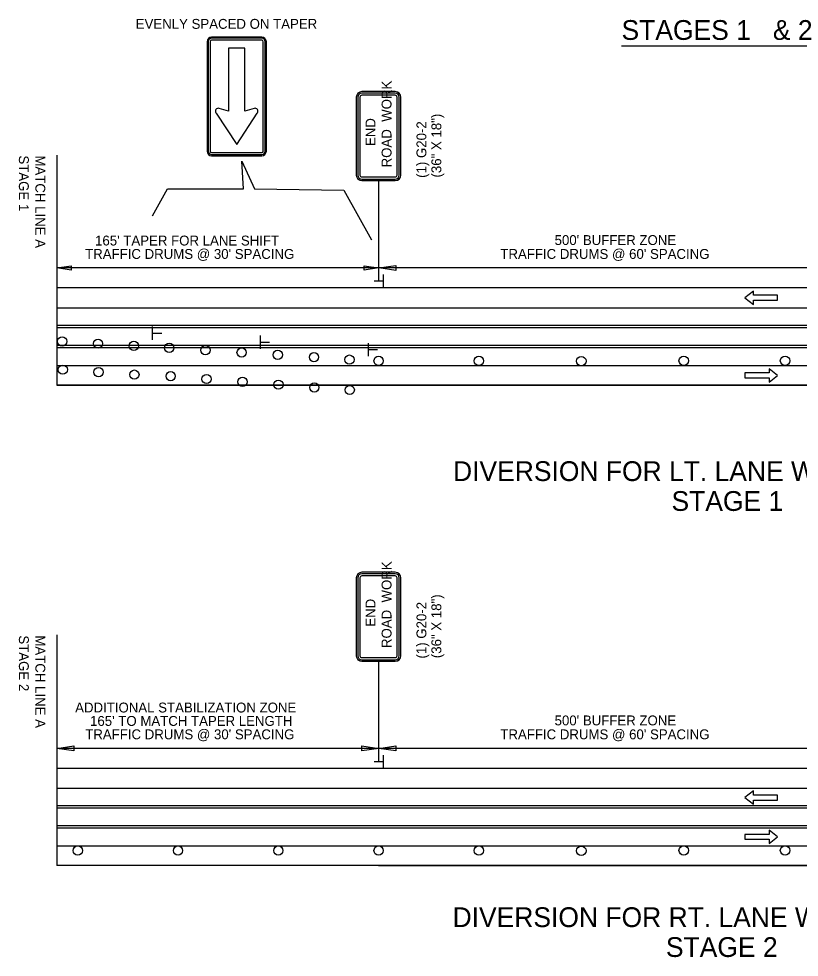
# Model space of a CAD drawing. Extents: x 1930579 to 1937984, y 596452 to 597630.
# Drawn here: x 1936470 to 1936944, y 596628 to 597198 of the extents above; entities that cross this region are included whole.
import ezdxf

# ---------------------------------------------------------------- set-up
doc = ezdxf.new("R2010")
doc.units = 0
for name, color, linetype in [('Default', 7, 'Continuous'), ('P_TC_Signs_Permanent', 7, 'Continuous'), ('P_TC_Signs_Temporary', 7, 'Continuous'), ('R_Border', 7, 'Continuous'), ('R_Striping', 7, 'Continuous')]:
    doc.layers.add(name, color=color, linetype=linetype)

msp = doc.modelspace()

# ---------------------------------------------------------------- linework, layer by layer
at = {"layer": 'Default'}
for p, q in [((1936835.84, 597181.22), (1936964.15, 597181.22)), ((1936493.11, 597114.97), (1936493.11, 596975.31)), ((1936493.11, 597046.45), (1936501.81, 597047.75)), ((1936688.44, 597046.45), (1936493.11, 597046.45)), ((1936501.81, 597045.15), (1936493.11, 597046.45)), ((1936501.81, 597047.75), (1936501.81, 597045.15)), ((1936679.75, 597045.15), (1936679.75, 597047.75)), ((1936679.75, 597047.75), (1936688.44, 597046.45)), ((1936688.44, 597046.45), (1936679.75, 597045.15)), ((1936997.05, 597046.45), (1936688.44, 597046.45)), ((1936688.53, 597046.45), (1936698.83, 597048)), ((1936698.83, 597044.9), (1936688.53, 597046.45)), ((1936698.83, 597048), (1936698.83, 597044.9)), ((1936691.23, 597042.43), (1936691.23, 597034.45)), ((1937498.74, 597034.31), (1936493.11, 597034.31)), ((1936691.12, 597038.47), (1936685.67, 597038.47)), ((1936493.11, 597022.31), (1937498.74, 597022.31)), ((1937498.74, 597011.52), (1936493.11, 597011.52)), ((1937498.74, 597010.14), (1936493.11, 597010.14)), ((1936551.31, 597002.87), (1936551.31, 597010.85)), ((1936551.43, 597006.84), (1936556.87, 597006.84)), ((1936616.72, 596997.46), (1936616.72, 597005.44)), ((1936616.84, 597001.42), (1936622.29, 597001.42)), ((1936682.29, 596992.94), (1936682.29, 597000.92)), ((1937498.74, 596999.34), (1936493.11, 596999.34)), ((1937498.74, 596998.03), (1936493.11, 596998.03)), ((1936682.4, 596996.91), (1936687.85, 596996.91)), ((1936493.11, 596987.31), (1937498.74, 596987.31)), ((1936493.11, 596975.31), (1936773.63, 596975.31)), ((1937498.74, 596975.31), (1936493.11, 596975.31)), ((1936757.75, 596975.31), (1937032.82, 596975.31)), ((1936493.11, 596823.85), (1936493.11, 596683.94)), ((1936688.44, 596765.87), (1936688.44, 596749.76)), ((1936493.11, 596755.08), (1936503.42, 596756.63)), ((1936503.42, 596756.63), (1936503.42, 596753.53)), ((1936678.23, 596753.53), (1936678.23, 596756.63)), ((1936678.23, 596756.63), (1936688.53, 596755.08)), ((1936688.53, 596755.08), (1936698.83, 596756.63)), ((1936698.83, 596756.63), (1936698.83, 596753.53)), ((1936688.53, 596755.08), (1936493.11, 596755.08)), ((1936503.42, 596753.53), (1936493.11, 596755.08)), ((1936688.53, 596755.08), (1936678.23, 596753.53)), ((1936997.05, 596755.08), (1936688.44, 596755.08)), ((1936698.83, 596753.53), (1936688.53, 596755.08)), ((1936691.23, 596750.89), (1936691.23, 596742.91)), ((1936691.12, 596746.92), (1936685.67, 596746.92)), ((1937498.74, 596742.94), (1936493.11, 596742.94)), ((1936493.11, 596730.94), (1937498.74, 596730.94)), ((1937498.74, 596720.15), (1936493.11, 596720.15)), ((1937498.74, 596718.77), (1936493.11, 596718.77)), ((1937498.74, 596707.98), (1936493.11, 596707.98)), ((1937498.74, 596706.66), (1936493.11, 596706.66)), ((1936493.11, 596695.94), (1937498.74, 596695.94)), ((1937498.74, 596683.94), (1936493.11, 596683.94)), ((1936688.44, 596683.94), (1936773.63, 596683.94)), ((1936757.75, 596683.94), (1937032.82, 596683.94))]:
    msp.add_line(p, q, dxfattribs=at)
for centre, radius in [((1936496.43, 597001.89), 2.81), ((1936518.18, 597000.54), 2.81), ((1936539.92, 596999.19), 2.81), ((1936561.41, 596998), 2.81), ((1936583.36, 596996.58), 2.81), ((1936605.32, 596995.17), 2.81), ((1936627.27, 596993.75), 2.81), ((1936649.22, 596992.34), 2.81), ((1936670.72, 596990.86), 2.81), ((1936688.44, 596990.1), 2.81), ((1936749.3, 596990.1), 2.87), ((1936811.44, 596989.95), 2.87), ((1936873.58, 596990.16), 2.87), ((1936935.06, 596990.17), 2.87), ((1936496.8, 596984.78), 2.81), ((1936518.53, 596983.27), 2.81), ((1936540.25, 596981.76), 2.81), ((1936562.28, 596980.82), 2.81), ((1936584.07, 596979.1), 2.81), ((1936605.86, 596977.39), 2.81), ((1936627.65, 596975.67), 2.81), ((1936649.45, 596973.95), 2.81), ((1936670.92, 596972.45), 2.81), ((1936505.88, 596693.1), 2.81), ((1936566.73, 596693.1), 2.81), ((1936627.59, 596693.1), 2.81), ((1936688.44, 596693.1), 2.81), ((1936749.3, 596693.1), 2.87), ((1936811.44, 596692.96), 2.87), ((1936873.58, 596693.16), 2.87), ((1936935.06, 596693.18), 2.87)]:
    msp.add_circle(centre, radius, dxfattribs=at)
at = {"layer": 'P_TC_Signs_Permanent'}
for p, q in [((1936584.33, 597183.71), (1936584.33, 597117.33)), ((1936585.08, 597183.71), (1936585.08, 597117.33)), ((1936586.2, 597183.71), (1936586.2, 597117.33)), ((1936617.51, 597186.52), (1936587.14, 597186.52)), ((1936617.51, 597185.77), (1936587.14, 597185.77)), ((1936617.51, 597184.65), (1936587.14, 597184.65)), ((1936618.45, 597117.33), (1936618.45, 597183.71)), ((1936619.58, 597117.33), (1936619.58, 597183.71)), ((1936620.33, 597117.33), (1936620.33, 597183.71)), ((1936587.14, 597116.4), (1936617.51, 597116.4)), ((1936587.14, 597115.27), (1936617.51, 597115.27)), ((1936587.14, 597114.52), (1936617.51, 597114.52))]:
    msp.add_line(p, q, dxfattribs=at)
for points in [[(1936612.96, 597143.22), (1936607.2, 597141.5), (1936607.2, 597179.77), (1936597.45, 597179.77), (1936597.45, 597141.5), (1936591.7, 597143.26)], [(1936589.88, 597140.26), (1936602.33, 597121.27), (1936614.73, 597140.27)]]:
    msp.add_lwpolyline(points, dxfattribs=at)
for centre, radius, start, end in [((1936587.14, 597183.71), 2.81, 90, 180), ((1936587.14, 597183.71), 2.06, 90, 180), ((1936587.14, 597183.71), 0.938, 90, 180), ((1936617.51, 597183.71), 2.81, 360, 90), ((1936617.51, 597183.71), 2.06, 360, 90), ((1936617.51, 597183.71), 0.937, 360, 90), ((1936591.21, 597141.53), 1.8, 74.0309, 213.4755), ((1936613.44, 597141.53), 1.76, 326.5994, 105.9691), ((1936527.15, 597099.16), 75, 33.2286, 33.4755), ((1936677.53, 597099.27), 75, 146.5994, 146.857), ((1936587.14, 597117.33), 2.81, 180, 270), ((1936587.14, 597117.33), 2.06, 180, 270), ((1936587.14, 597117.33), 0.938, 180, 270), ((1936617.51, 597117.33), 2.81, 270, 360), ((1936617.51, 597117.33), 2.06, 270, 360), ((1936617.51, 597117.33), 0.938, 270, 360)]:
    msp.add_arc(centre, radius, start, end, dxfattribs=at)
at = {"layer": 'P_TC_Signs_Temporary'}
for p, q in [((1936674.89, 597150.04), (1936674.89, 597102.79)), ((1936675.83, 597150.04), (1936675.83, 597102.79)), ((1936677.14, 597150.04), (1936677.14, 597102.79)), ((1936698.52, 597153.42), (1936678.27, 597153.42)), ((1936698.52, 597152.48), (1936678.27, 597152.48)), ((1936698.52, 597151.17), (1936678.27, 597151.17)), ((1936699.64, 597102.79), (1936699.64, 597150.04)), ((1936700.96, 597102.79), (1936700.96, 597150.04)), ((1936701.89, 597102.79), (1936701.89, 597150.04)), ((1936678.27, 597101.67), (1936698.52, 597101.67)), ((1936678.27, 597100.36), (1936698.52, 597100.36)), ((1936678.27, 597099.42), (1936698.52, 597099.42)), ((1936674.89, 596858.5), (1936674.89, 596811.25)), ((1936675.83, 596858.5), (1936675.83, 596811.25)), ((1936677.14, 596858.5), (1936677.14, 596811.25)), ((1936698.52, 596861.87), (1936678.27, 596861.87)), ((1936698.52, 596860.93), (1936678.27, 596860.93)), ((1936698.52, 596859.62), (1936678.27, 596859.62)), ((1936699.64, 596811.25), (1936699.64, 596858.5)), ((1936700.96, 596811.25), (1936700.96, 596858.5)), ((1936701.89, 596811.25), (1936701.89, 596858.5)), ((1936678.27, 596810.12), (1936698.52, 596810.12)), ((1936678.27, 596808.81), (1936698.52, 596808.81)), ((1936678.27, 596807.87), (1936698.52, 596807.87))]:
    msp.add_line(p, q, dxfattribs=at)
for centre, radius, start, end in [((1936678.27, 597150.04), 3.38, 90, 180), ((1936678.27, 597150.04), 2.44, 90, 180), ((1936678.27, 597150.04), 1.13, 90, 180), ((1936698.52, 597150.04), 3.38, 360, 90), ((1936698.52, 597150.04), 2.44, 360, 90), ((1936698.52, 597150.04), 1.13, 360, 90), ((1936678.27, 597102.79), 3.38, 180, 270), ((1936678.27, 597102.79), 2.44, 180, 270), ((1936678.27, 597102.79), 1.13, 180, 270), ((1936698.52, 597102.79), 2.44, 270, 360), ((1936698.52, 597102.79), 1.13, 270, 360), ((1936698.52, 597102.79), 3.38, 270, 360), ((1936678.27, 596858.5), 3.38, 90, 180), ((1936678.27, 596858.5), 2.44, 90, 180), ((1936678.27, 596858.5), 1.13, 90, 180), ((1936698.52, 596858.5), 3.38, 360, 90), ((1936698.52, 596858.5), 2.44, 360, 90), ((1936698.52, 596858.5), 1.13, 360, 90), ((1936678.27, 596811.25), 3.38, 180, 270), ((1936678.27, 596811.25), 2.44, 180, 270), ((1936678.27, 596811.25), 1.13, 180, 270), ((1936698.52, 596811.25), 2.44, 270, 360), ((1936698.52, 596811.25), 1.13, 270, 360), ((1936698.52, 596811.25), 3.38, 270, 360)]:
    msp.add_arc(centre, radius, start, end, dxfattribs=at)
at = {"layer": 'R_Border'}
for p, q in [((1936688.39, 597099.42), (1936688.39, 597038.47)), ((1936688.39, 596807.87), (1936688.39, 596746.92))]:
    msp.add_line(p, q, dxfattribs=at)
msp.add_lwpolyline([(1936551.31, 597078.12), (1936560.31, 597094.42), (1936606.55, 597094.42), (1936605.35, 597111.31), (1936613.15, 597094.42), (1936667.35, 597093.63), (1936684.23, 597063.48)], dxfattribs=at)
at = {"layer": 'R_Striping'}
for points in [[(1936915.85, 597032.39), (1936910.66, 597028.39), (1936915.85, 597024.39), (1936915.85, 597026.89), (1936930.56, 597026.89), (1936930.56, 597029.89), (1936915.85, 597029.89)], [(1936925.37, 596977.26), (1936930.56, 596981.26), (1936925.37, 596985.26), (1936925.37, 596982.76), (1936910.66, 596982.76), (1936910.66, 596979.76), (1936925.37, 596979.76)], [(1936915.85, 596729.24), (1936910.66, 596725.24), (1936915.85, 596721.24), (1936915.85, 596723.74), (1936930.56, 596723.74), (1936930.56, 596726.74), (1936915.85, 596726.74)], [(1936925.37, 596697.41), (1936930.56, 596701.41), (1936925.37, 596705.41), (1936925.37, 596702.91), (1936910.66, 596702.91), (1936910.66, 596699.91), (1936925.37, 596699.91)]]:
    msp.add_lwpolyline(points, close=True, dxfattribs=at)

# ---------------------------------------------------------------- texts
at = {"layer": 'Default'}
for s, height, rotation, p in [('STAGES 1   & 2', 12, 360, (1936835.84, 597184.79)), ('STAGE 1', 6, 270, (1936470.18, 597114.71)), ('MATCH LINE A ', 6, 270, (1936480.18, 597114.71)), ("165' TAPER FOR LANE SHIFT", 6, 360, (1936516.4, 597060.08)), ("500' BUFFER ZONE", 6, 360, (1936795.24, 597060.38)), ("TRAFFIC DRUMS @ 30' SPACING", 6, 360, (1936510.37, 597051.95)), ("TRAFFIC DRUMS @ 60' SPACING", 6, 360, (1936762.31, 597051.95)), ('DIVERSION FOR LT. LANE WORK ZONE', 12, 360, (1936733.6, 596917.22)), ('STAGE 1', 12, 360, (1936866.17, 596899.1)), ('STAGE 2', 6, 270, (1936470.18, 596823.6)), ('MATCH LINE A ', 6, 270, (1936480.18, 596823.6)), ('ADDITIONAL STABILIZATION ZONE', 6, 360, (1936504.32, 596776.83)), ("165' TO MATCH TAPER LENGTH", 6, 360, (1936513.36, 596768.71)), ("500' BUFFER ZONE", 6, 360, (1936795.24, 596769.01)), ("TRAFFIC DRUMS @ 30' SPACING", 6, 360, (1936510.44, 596760.58)), ("TRAFFIC DRUMS @ 60' SPACING", 6, 360, (1936762.31, 596760.58)), ('DIVERSION FOR RT. LANE WORK ZONE', 12, 360, (1936733.32, 596646.67)), ('STAGE 2', 12, 360, (1936862.77, 596628.55))]:
    msp.add_text(s, height=height, rotation=rotation, dxfattribs=at).set_placement(p)
at = {"layer": 'P_TC_Signs_Temporary'}
for s, p in [('ROAD  WORK', (1936696.27, 597107.46)), ('END', (1936686.52, 597120.39)), ('ROAD  WORK', (1936696.27, 596815.91)), ('END', (1936686.52, 596828.84))]:
    msp.add_text(s, height=6, rotation=90, dxfattribs=at).set_placement(p)
at = {"layer": 'R_Border'}
for s, rotation, p in [('EVENLY SPACED ON TAPER', 0.0075, (1936541.07, 597191.5)), ('(36" X 18")', 90, (1936726.48, 597101.31)), ('(1) G20-2', 90, (1936717.43, 597101.1)), ('(36" X 18")', 90, (1936726.48, 596809.77)), ('(1) G20-2', 90, (1936717.43, 596809.55))]:
    msp.add_text(s, height=6, rotation=rotation, dxfattribs=at).set_placement(p)

doc.saveas('drawing.dxf')
